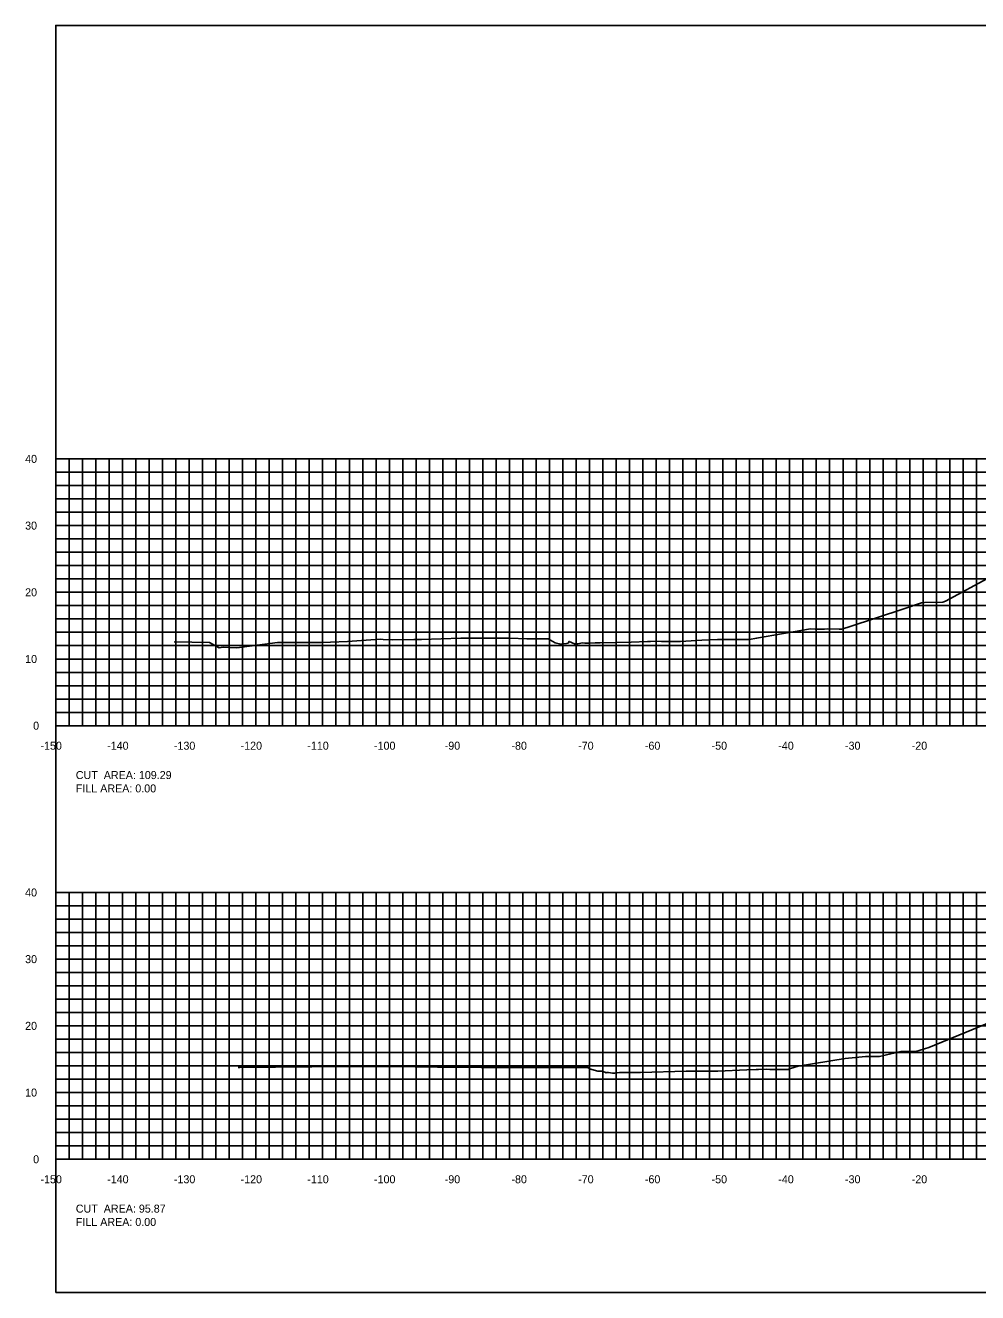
# Model space of a CAD drawing. Extents: x 1797652 to 1804159, y 242516 to 246906.
# Drawn here: x 1803169.9 to 1803312.7, y 242516 to 242706 of the extents above; entities that cross this region are included whole.
import ezdxf

# ---------------------------------------------------------------- set-up
doc = ezdxf.new("R2010")
doc.units = 0
for name, color, linetype in [('10', 7, 'Continuous'), ('31', 7, 'Continuous'), ('60', 7, 'Continuous'), ('Level 62', 7, 'Continuous'), ('M-ROADS', 7, 'Continuous')]:
    doc.layers.add(name, color=color, linetype=linetype)

msp = doc.modelspace()

# ---------------------------------------------------------------- linework, layer by layer
msp.add_lwpolyline([(1803174.49, 242516), (1803474.49, 242516), (1803474.49, 242706), (1803174.49, 242706)], close=True)
at = {"layer": '60'}
for p, q in [((1803174.43, 242641), (1803174.49, 242641)), ((1803174.49, 242601), (1803174.49, 242641)), ((1803174.43, 242631), (1803174.49, 242631)), ((1803174.43, 242621), (1803174.49, 242621)), ((1803174.43, 242611), (1803174.49, 242611)), ((1803174.43, 242601), (1803174.49, 242601)), ((1803174.49, 242601), (1803474.49, 242601)), ((1803174.49, 242600.94), (1803174.49, 242601)), ((1803184.49, 242600.94), (1803184.49, 242601)), ((1803194.49, 242600.94), (1803194.49, 242601)), ((1803204.49, 242600.94), (1803204.49, 242601)), ((1803214.49, 242600.94), (1803214.49, 242601)), ((1803224.49, 242600.94), (1803224.49, 242601)), ((1803234.49, 242600.94), (1803234.49, 242601)), ((1803244.49, 242600.94), (1803244.49, 242601)), ((1803254.49, 242600.94), (1803254.49, 242601)), ((1803264.49, 242600.94), (1803264.49, 242601)), ((1803274.49, 242600.94), (1803274.49, 242601)), ((1803284.49, 242600.94), (1803284.49, 242601)), ((1803294.49, 242600.94), (1803294.49, 242601)), ((1803304.49, 242600.94), (1803304.49, 242601)), ((1803174.43, 242576), (1803174.49, 242576)), ((1803174.49, 242536), (1803174.49, 242576)), ((1803174.43, 242566), (1803174.49, 242566)), ((1803174.43, 242556), (1803174.49, 242556)), ((1803174.43, 242546), (1803174.49, 242546)), ((1803174.43, 242536), (1803174.49, 242536)), ((1803174.49, 242536), (1803474.49, 242536)), ((1803174.49, 242535.94), (1803174.49, 242536)), ((1803184.49, 242535.94), (1803184.49, 242536)), ((1803194.49, 242535.94), (1803194.49, 242536)), ((1803204.49, 242535.94), (1803204.49, 242536)), ((1803214.49, 242535.94), (1803214.49, 242536)), ((1803224.49, 242535.94), (1803224.49, 242536)), ((1803234.49, 242535.94), (1803234.49, 242536)), ((1803244.49, 242535.94), (1803244.49, 242536)), ((1803254.49, 242535.94), (1803254.49, 242536)), ((1803264.49, 242535.94), (1803264.49, 242536)), ((1803274.49, 242535.94), (1803274.49, 242536)), ((1803284.49, 242535.94), (1803284.49, 242536)), ((1803294.49, 242535.94), (1803294.49, 242536)), ((1803304.49, 242535.94), (1803304.49, 242536))]:
    msp.add_line(p, q, dxfattribs=at)
at = {"layer": 'Level 62'}
for p, q in [((1803174.49, 242641), (1803474.49, 242641)), ((1803174.49, 242601), (1803174.49, 242641)), ((1803176.49, 242601), (1803176.49, 242641)), ((1803178.49, 242601), (1803178.49, 242641)), ((1803180.49, 242601), (1803180.49, 242641)), ((1803182.49, 242601), (1803182.49, 242641)), ((1803184.49, 242601), (1803184.49, 242641)), ((1803186.49, 242601), (1803186.49, 242641)), ((1803188.49, 242601), (1803188.49, 242641)), ((1803190.49, 242601), (1803190.49, 242641)), ((1803192.49, 242601), (1803192.49, 242641)), ((1803194.49, 242601), (1803194.49, 242641)), ((1803196.49, 242601), (1803196.49, 242641)), ((1803198.49, 242601), (1803198.49, 242641)), ((1803200.49, 242601), (1803200.49, 242641)), ((1803202.49, 242601), (1803202.49, 242641)), ((1803204.49, 242601), (1803204.49, 242641)), ((1803206.49, 242601), (1803206.49, 242641)), ((1803208.49, 242601), (1803208.49, 242641)), ((1803210.49, 242601), (1803210.49, 242641)), ((1803212.49, 242601), (1803212.49, 242641)), ((1803214.49, 242601), (1803214.49, 242641)), ((1803216.49, 242601), (1803216.49, 242641)), ((1803218.49, 242601), (1803218.49, 242641)), ((1803220.49, 242601), (1803220.49, 242641)), ((1803222.49, 242601), (1803222.49, 242641)), ((1803224.49, 242601), (1803224.49, 242641)), ((1803226.49, 242601), (1803226.49, 242641)), ((1803228.49, 242601), (1803228.49, 242641)), ((1803230.49, 242601), (1803230.49, 242641)), ((1803232.49, 242601), (1803232.49, 242641)), ((1803234.49, 242601), (1803234.49, 242641)), ((1803236.49, 242601), (1803236.49, 242641)), ((1803238.49, 242601), (1803238.49, 242641)), ((1803240.49, 242601), (1803240.49, 242641)), ((1803242.49, 242601), (1803242.49, 242641)), ((1803244.49, 242601), (1803244.49, 242641)), ((1803246.49, 242601), (1803246.49, 242641)), ((1803248.49, 242601), (1803248.49, 242641)), ((1803250.49, 242601), (1803250.49, 242641)), ((1803252.49, 242601), (1803252.49, 242641)), ((1803254.49, 242601), (1803254.49, 242641)), ((1803256.49, 242601), (1803256.49, 242641)), ((1803258.49, 242601), (1803258.49, 242641)), ((1803260.49, 242601), (1803260.49, 242641)), ((1803262.49, 242601), (1803262.49, 242641)), ((1803264.49, 242601), (1803264.49, 242641)), ((1803266.49, 242601), (1803266.49, 242641)), ((1803268.49, 242601), (1803268.49, 242641)), ((1803270.49, 242601), (1803270.49, 242641)), ((1803272.49, 242601), (1803272.49, 242641)), ((1803274.49, 242601), (1803274.49, 242641)), ((1803276.49, 242601), (1803276.49, 242641)), ((1803278.49, 242601), (1803278.49, 242641)), ((1803280.49, 242601), (1803280.49, 242641)), ((1803282.49, 242601), (1803282.49, 242641)), ((1803284.49, 242601), (1803284.49, 242641)), ((1803286.49, 242601), (1803286.49, 242641)), ((1803288.49, 242601), (1803288.49, 242641)), ((1803290.49, 242601), (1803290.49, 242641)), ((1803292.49, 242601), (1803292.49, 242641)), ((1803294.49, 242601), (1803294.49, 242641)), ((1803296.49, 242601), (1803296.49, 242641)), ((1803298.49, 242601), (1803298.49, 242641)), ((1803300.49, 242601), (1803300.49, 242641)), ((1803302.49, 242601), (1803302.49, 242641)), ((1803304.49, 242601), (1803304.49, 242641)), ((1803306.49, 242601), (1803306.49, 242641)), ((1803308.49, 242601), (1803308.49, 242641)), ((1803310.49, 242601), (1803310.49, 242641)), ((1803312.49, 242601), (1803312.49, 242641)), ((1803174.49, 242639), (1803474.49, 242639)), ((1803174.49, 242637), (1803474.49, 242637)), ((1803174.49, 242635), (1803474.49, 242635)), ((1803174.49, 242633), (1803474.49, 242633)), ((1803174.49, 242631), (1803474.49, 242631)), ((1803174.49, 242629), (1803474.49, 242629)), ((1803174.49, 242627), (1803474.49, 242627)), ((1803174.49, 242625), (1803474.49, 242625)), ((1803174.49, 242623), (1803474.49, 242623)), ((1803174.49, 242621), (1803474.49, 242621)), ((1803174.49, 242619), (1803474.49, 242619)), ((1803174.49, 242617), (1803474.49, 242617)), ((1803174.49, 242615), (1803474.49, 242615)), ((1803174.49, 242613), (1803474.49, 242613)), ((1803174.49, 242611), (1803474.49, 242611)), ((1803174.49, 242609), (1803474.49, 242609)), ((1803174.49, 242607), (1803474.49, 242607)), ((1803174.49, 242605), (1803474.49, 242605)), ((1803174.49, 242603), (1803474.49, 242603)), ((1803174.49, 242601), (1803474.49, 242601)), ((1803174.49, 242576), (1803474.49, 242576)), ((1803174.49, 242536), (1803174.49, 242576)), ((1803176.49, 242536), (1803176.49, 242576)), ((1803178.49, 242536), (1803178.49, 242576)), ((1803180.49, 242536), (1803180.49, 242576)), ((1803182.49, 242536), (1803182.49, 242576)), ((1803184.49, 242536), (1803184.49, 242576)), ((1803186.49, 242536), (1803186.49, 242576)), ((1803188.49, 242536), (1803188.49, 242576)), ((1803190.49, 242536), (1803190.49, 242576)), ((1803192.49, 242536), (1803192.49, 242576)), ((1803194.49, 242536), (1803194.49, 242576)), ((1803196.49, 242536), (1803196.49, 242576)), ((1803198.49, 242536), (1803198.49, 242576)), ((1803200.49, 242536), (1803200.49, 242576)), ((1803202.49, 242536), (1803202.49, 242576)), ((1803204.49, 242536), (1803204.49, 242576)), ((1803206.49, 242536), (1803206.49, 242576)), ((1803208.49, 242536), (1803208.49, 242576)), ((1803210.49, 242536), (1803210.49, 242576)), ((1803212.49, 242536), (1803212.49, 242576)), ((1803214.49, 242536), (1803214.49, 242576)), ((1803216.49, 242536), (1803216.49, 242576)), ((1803218.49, 242536), (1803218.49, 242576)), ((1803220.49, 242536), (1803220.49, 242576)), ((1803222.49, 242536), (1803222.49, 242576)), ((1803224.49, 242536), (1803224.49, 242576)), ((1803226.49, 242536), (1803226.49, 242576)), ((1803228.49, 242536), (1803228.49, 242576)), ((1803230.49, 242536), (1803230.49, 242576)), ((1803232.49, 242536), (1803232.49, 242576)), ((1803234.49, 242536), (1803234.49, 242576)), ((1803236.49, 242536), (1803236.49, 242576)), ((1803238.49, 242536), (1803238.49, 242576)), ((1803240.49, 242536), (1803240.49, 242576)), ((1803242.49, 242536), (1803242.49, 242576)), ((1803244.49, 242536), (1803244.49, 242576)), ((1803246.49, 242536), (1803246.49, 242576)), ((1803248.49, 242536), (1803248.49, 242576)), ((1803250.49, 242536), (1803250.49, 242576)), ((1803252.49, 242536), (1803252.49, 242576)), ((1803254.49, 242536), (1803254.49, 242576)), ((1803256.49, 242536), (1803256.49, 242576)), ((1803258.49, 242536), (1803258.49, 242576)), ((1803260.49, 242536), (1803260.49, 242576)), ((1803262.49, 242536), (1803262.49, 242576)), ((1803264.49, 242536), (1803264.49, 242576)), ((1803266.49, 242536), (1803266.49, 242576)), ((1803268.49, 242536), (1803268.49, 242576)), ((1803270.49, 242536), (1803270.49, 242576)), ((1803272.49, 242536), (1803272.49, 242576)), ((1803274.49, 242536), (1803274.49, 242576)), ((1803276.49, 242536), (1803276.49, 242576)), ((1803278.49, 242536), (1803278.49, 242576)), ((1803280.49, 242536), (1803280.49, 242576)), ((1803282.49, 242536), (1803282.49, 242576)), ((1803284.49, 242536), (1803284.49, 242576)), ((1803286.49, 242536), (1803286.49, 242576)), ((1803288.49, 242536), (1803288.49, 242576)), ((1803290.49, 242536), (1803290.49, 242576)), ((1803292.49, 242536), (1803292.49, 242576)), ((1803294.49, 242536), (1803294.49, 242576)), ((1803296.49, 242536), (1803296.49, 242576)), ((1803298.49, 242536), (1803298.49, 242576)), ((1803300.49, 242536), (1803300.49, 242576)), ((1803302.49, 242536), (1803302.49, 242576)), ((1803304.49, 242536), (1803304.49, 242576)), ((1803306.49, 242536), (1803306.49, 242576)), ((1803308.49, 242536), (1803308.49, 242576)), ((1803310.49, 242536), (1803310.49, 242576)), ((1803312.49, 242536), (1803312.49, 242576)), ((1803174.49, 242574), (1803474.49, 242574)), ((1803174.49, 242572), (1803474.49, 242572)), ((1803174.49, 242570), (1803474.49, 242570)), ((1803174.49, 242568), (1803474.49, 242568)), ((1803174.49, 242566), (1803474.49, 242566)), ((1803174.49, 242564), (1803474.49, 242564)), ((1803174.49, 242562), (1803474.49, 242562)), ((1803174.49, 242560), (1803474.49, 242560)), ((1803174.49, 242558), (1803474.49, 242558)), ((1803174.49, 242556), (1803474.49, 242556)), ((1803174.49, 242554), (1803474.49, 242554)), ((1803174.49, 242552), (1803474.49, 242552)), ((1803174.49, 242550), (1803474.49, 242550)), ((1803174.49, 242548), (1803474.49, 242548)), ((1803174.49, 242546), (1803474.49, 242546)), ((1803174.49, 242544), (1803474.49, 242544)), ((1803174.49, 242542), (1803474.49, 242542)), ((1803174.49, 242540), (1803474.49, 242540)), ((1803174.49, 242538), (1803474.49, 242538)), ((1803174.49, 242536), (1803474.49, 242536))]:
    msp.add_line(p, q, dxfattribs=at)
at = {"layer": 'M-ROADS'}
for points in [[(1803192.25, 242613.57), (1803197.54, 242613.45), (1803198.96, 242612.66), (1803199.57, 242612.75), (1803201.63, 242612.66), (1803207.72, 242613.48), (1803208.76, 242613.47), (1803210.14, 242613.47), (1803211, 242613.47), (1803212.04, 242613.47), (1803212.18, 242613.47), (1803212.3, 242613.47), (1803212.79, 242613.47), (1803214.29, 242613.47), (1803215.68, 242613.52), (1803218.21, 242613.62), (1803223.1, 242613.95), (1803223.56, 242613.93), (1803224.98, 242613.89), (1803228.18, 242613.9), (1803229.32, 242613.91), (1803235.18, 242614.14), (1803242.55, 242614.13), (1803245.11, 242614.03), (1803246.91, 242614.04), (1803248.1, 242614), (1803248.27, 242614), (1803249.33, 242613.41), (1803250.19, 242613.23), (1803251.03, 242613.32), (1803251.28, 242613.35), (1803251.44, 242613.64), (1803252.26, 242613.26), (1803252.76, 242613.29), (1803253.43, 242613.4), (1803253.81, 242613.39), (1803254.4, 242613.39), (1803255.32, 242613.4), (1803256.09, 242613.4), (1803260.73, 242613.54), (1803263.17, 242613.62), (1803263.61, 242613.64), (1803264.5, 242613.67), (1803265.27, 242613.64), (1803266.22, 242613.61), (1803266.3, 242613.61), (1803266.35, 242613.61), (1803267.97, 242613.64), (1803268.14, 242613.64), (1803271.34, 242613.8), (1803273.67, 242613.91), (1803274.92, 242613.93), (1803275.35, 242613.94), (1803275.41, 242613.94), (1803275.56, 242613.93), (1803276.44, 242613.91), (1803276.78, 242613.9), (1803278.21, 242613.92), (1803278.46, 242613.92), (1803279.53, 242614.1), (1803287.61, 242615.52), (1803288.34, 242615.47), (1803289.7, 242615.47), (1803290.21, 242615.51), (1803291.91, 242615.47), (1803292.24, 242615.47), (1803292.63, 242615.59), (1803293.43, 242615.83), (1803301.63, 242618.52), (1803304.28, 242619.44), (1803304.7, 242619.45), (1803307.47, 242619.53), (1803307.86, 242619.66), (1803314.68, 242623.36)], [(1803201.82, 242549.77), (1803202.08, 242549.77), (1803202.32, 242549.81), (1803203.62, 242549.82), (1803203.78, 242549.82), (1803203.93, 242549.82), (1803207.41, 242549.82), (1803218.34, 242549.93), (1803221.31, 242549.93), (1803222.25, 242549.93), (1803225.02, 242549.93), (1803231.7, 242549.83), (1803238.26, 242549.76), (1803240.22, 242549.76), (1803241.81, 242549.76), (1803251.29, 242549.75), (1803252.36, 242549.75), (1803253.96, 242549.75), (1803254.23, 242549.75), (1803254.51, 242549.58), (1803255.73, 242549.19), (1803256.43, 242549.22), (1803257.01, 242548.98), (1803257.09, 242549), (1803257.32, 242549), (1803257.96, 242548.92), (1803258.27, 242548.9), (1803258.97, 242549), (1803259.4, 242549), (1803259.94, 242548.99), (1803260.26, 242548.99), (1803261.81, 242549), (1803261.86, 242549), (1803262.14, 242549.01), (1803268.99, 242549.2), (1803270.23, 242549.21), (1803270.59, 242549.21), (1803271.22, 242549.21), (1803271.41, 242549.21), (1803272.15, 242549.19), (1803272.7, 242549.2), (1803273.75, 242549.21), (1803278.08, 242549.41), (1803279.49, 242549.47), (1803279.83, 242549.47), (1803281.09, 242549.49), (1803281.54, 242549.48), (1803282.27, 242549.48), (1803282.51, 242549.48), (1803282.65, 242549.48), (1803283.39, 242549.48), (1803284.25, 242549.48), (1803284.64, 242549.6), (1803285.75, 242549.94), (1803292.82, 242551.1), (1803294.34, 242551.27), (1803295.87, 242551.43), (1803297.73, 242551.43), (1803297.96, 242551.43), (1803299.64, 242551.81), (1803301.16, 242552.15), (1803301.62, 242552.15), (1803303.41, 242552.15), (1803305.36, 242552.76), (1803311.78, 242555.42), (1803317.34, 242557.7)]]:
    msp.add_lwpolyline(points, dxfattribs=at)

# ---------------------------------------------------------------- texts
at = {"layer": '10'}
for s, p in [('-150', (1803172.19, 242597.4)), ('-140', (1803182.19, 242597.4)), ('-130', (1803192.19, 242597.4)), ('-120', (1803202.19, 242597.4)), ('-110', (1803212.19, 242597.4)), ('-100', (1803222.19, 242597.4)), ('-90', (1803232.79, 242597.4)), ('-80', (1803242.79, 242597.4)), ('-70', (1803252.79, 242597.4)), ('-60', (1803262.79, 242597.4)), ('-50', (1803272.79, 242597.4)), ('-40', (1803282.79, 242597.4)), ('-30', (1803292.79, 242597.4)), ('-20', (1803302.79, 242597.4)), ('CUT  AREA: 109.29', (1803177.49, 242593)), ('FILL AREA: 0.00', (1803177.49, 242591)), ('-150', (1803172.19, 242532.4)), ('-140', (1803182.19, 242532.4)), ('-130', (1803192.19, 242532.4)), ('-120', (1803202.19, 242532.4)), ('-110', (1803212.19, 242532.4)), ('-100', (1803222.19, 242532.4)), ('-90', (1803232.79, 242532.4)), ('-80', (1803242.79, 242532.4)), ('-70', (1803252.79, 242532.4)), ('-60', (1803262.79, 242532.4)), ('-50', (1803272.79, 242532.4)), ('-40', (1803282.79, 242532.4)), ('-30', (1803292.79, 242532.4)), ('-20', (1803302.79, 242532.4)), ('CUT  AREA: 95.87', (1803177.49, 242528)), ('FILL AREA: 0.00', (1803177.49, 242526))]:
    msp.add_text(s, height=1.2, dxfattribs=at).set_placement(p)
at = {"layer": '31'}
for s, p in [('40', (1803169.89, 242640.4)), ('30', (1803169.89, 242630.4)), ('20', (1803169.89, 242620.4)), ('10', (1803169.89, 242610.4)), ('0', (1803171.09, 242600.4)), ('40', (1803169.89, 242575.4)), ('30', (1803169.89, 242565.4)), ('20', (1803169.89, 242555.4)), ('10', (1803169.89, 242545.4)), ('0', (1803171.09, 242535.4))]:
    msp.add_text(s, height=1.2, dxfattribs=at).set_placement(p)
at = {"layer": '60'}
for p in [(1803174.49, 242601), (1803174.49, 242536)]:
    msp.add_text('-', height=0.0001, dxfattribs=at).set_placement(p)

doc.saveas('drawing.dxf')
